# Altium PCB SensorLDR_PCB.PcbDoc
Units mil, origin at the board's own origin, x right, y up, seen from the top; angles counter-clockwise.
Board outline 6000 x 4000 mil, 2 copper layers (Top Layer, Bottom Layer); 19 components, 11 nets, 54 pads, 0 vias.
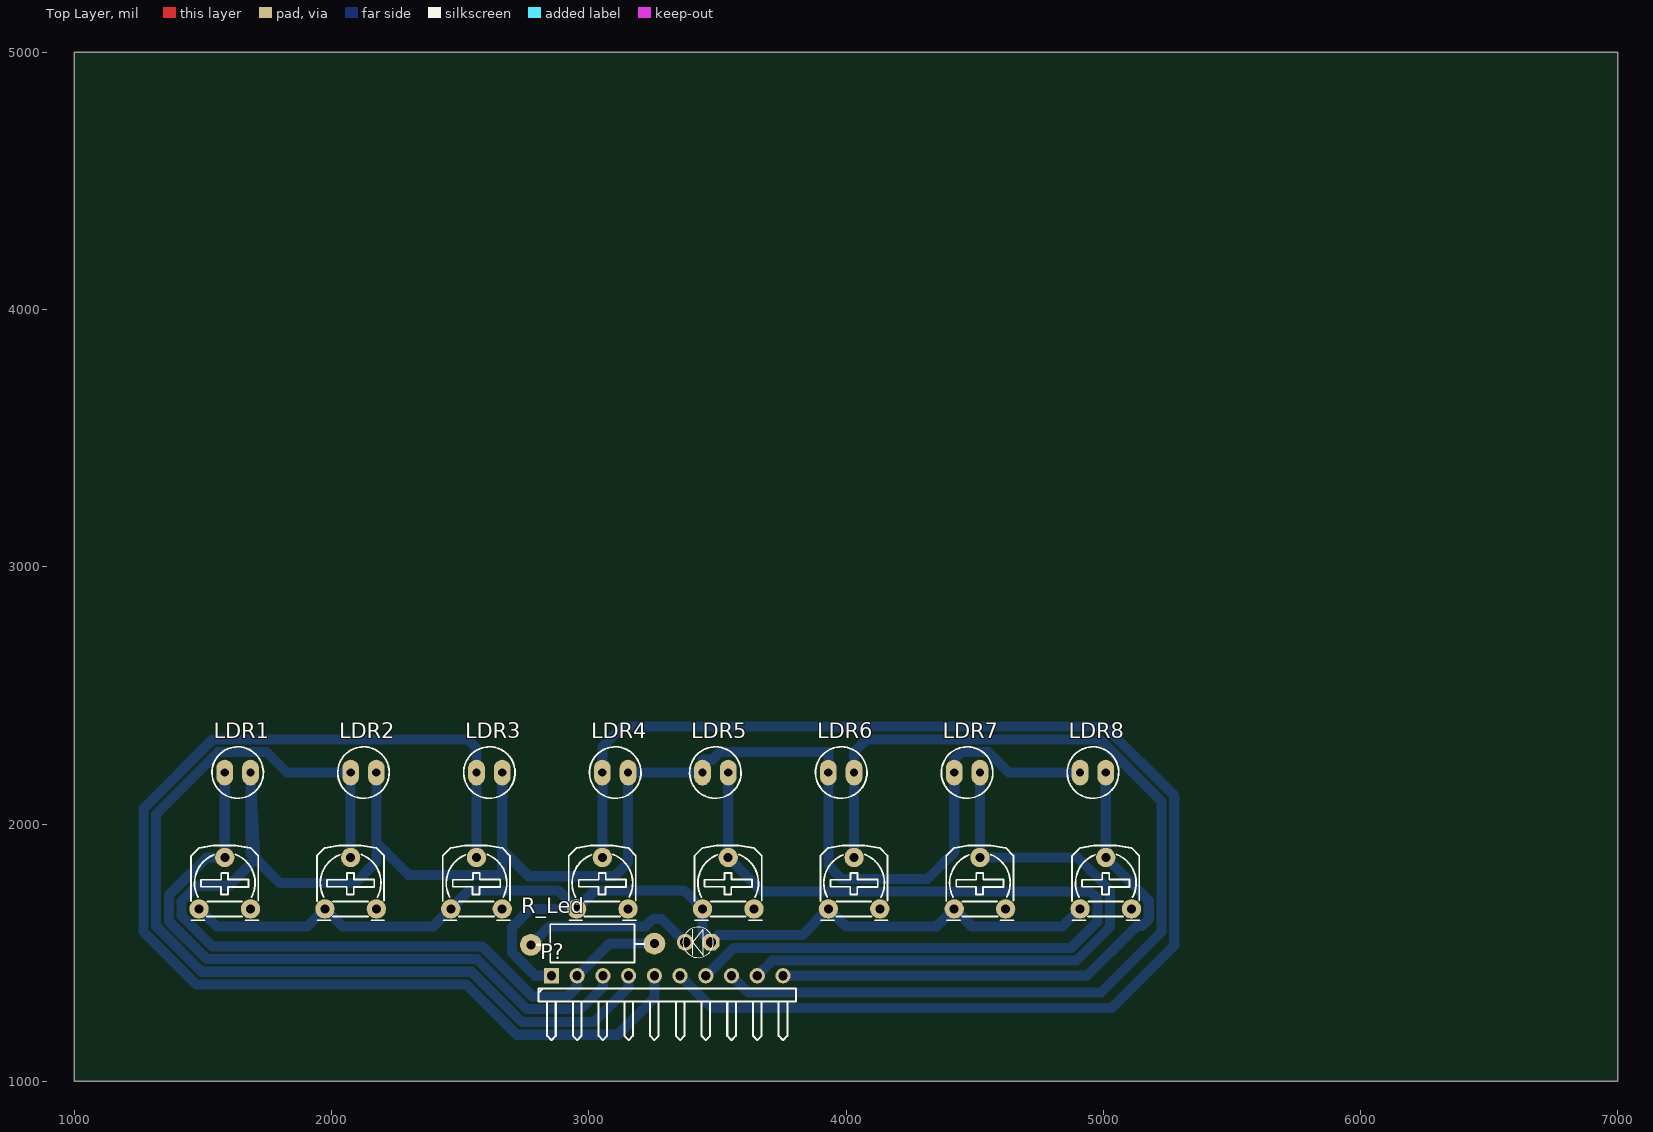
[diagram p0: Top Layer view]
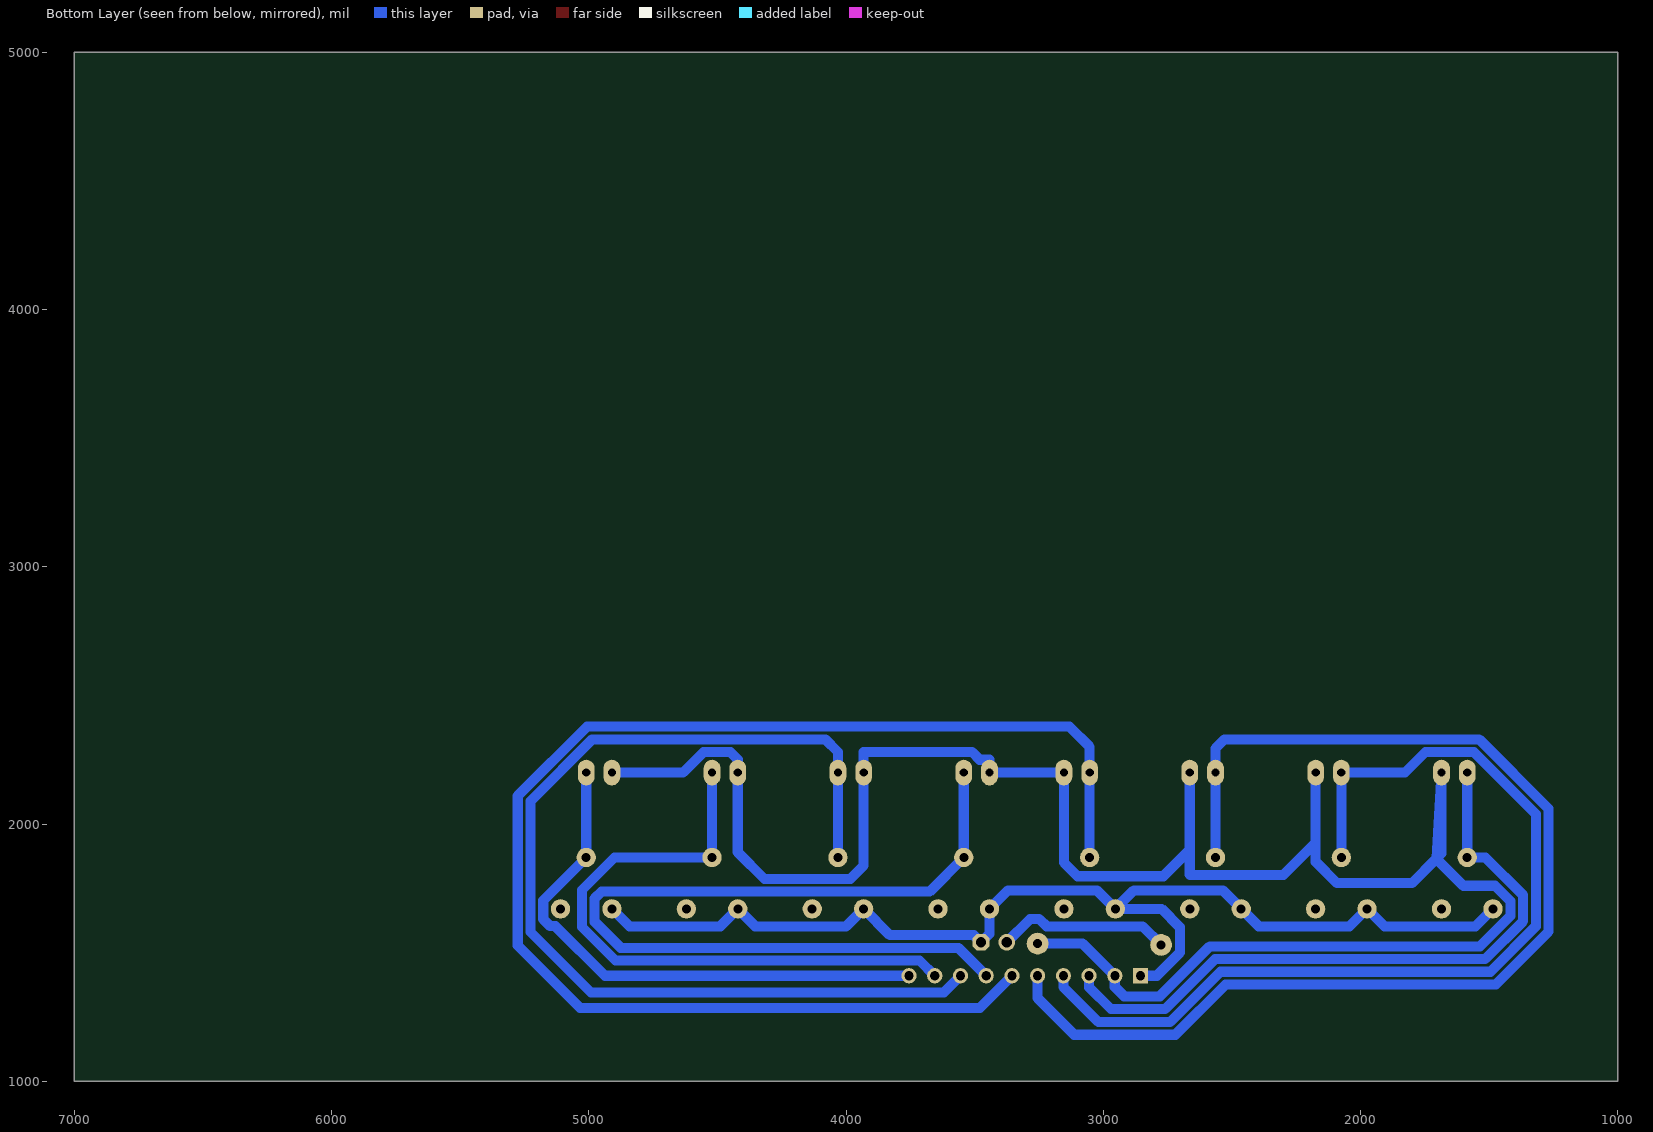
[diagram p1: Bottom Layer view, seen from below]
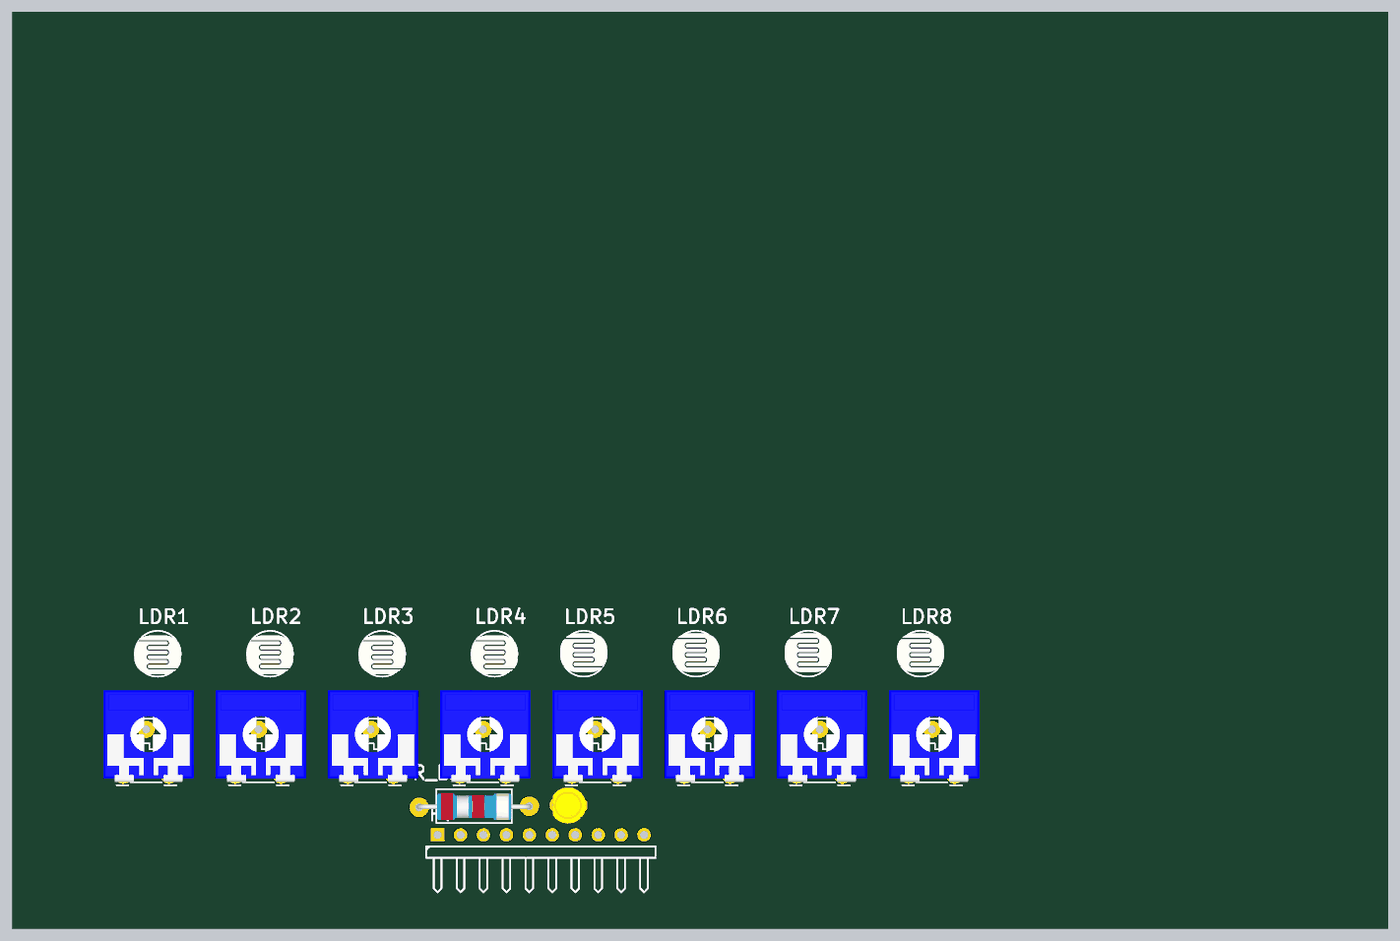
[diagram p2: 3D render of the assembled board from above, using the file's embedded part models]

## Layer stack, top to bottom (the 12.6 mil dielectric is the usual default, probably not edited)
Top Solder: solder mask 0.4, Solder Resist, Dk 3.5
Top Layer: signal copper 1.4
Dielectric 1: dielectric 12.6, FR-4, Dk 4.8
Bottom Layer: signal copper 1.4
Bottom Solder: solder mask 0.4, Solder Resist, Dk 3.5

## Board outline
1000,1000 7000,1000 7000,5000 1000,5000

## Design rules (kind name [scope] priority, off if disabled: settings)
Clearance [All] p1: gap=10 ignorepadtopadclearanceinfootprint=FALSE except(0: Arc-Hole Track-Hole SMDPad-Hole THPad-Hole Via-Hole Fill-Hole Poly-Hole Region-Hole Text-Hole)
PolygonConnect [All] p1: connectstyle=Relief reliefconductorwidth=10 reliefentries=4 polygonreliefangle="90 Angle" airgapwidth=10
RoutingLayers [All] p1: top layer_v5=FALSE bottom layer_v5=TRUE
RoutingVias [All] p1: holewidth=28 width=50 viastyle="Through Hole" minholewidth=28 minwidth=50 maxholewidth=28 maxwidth=50
SolderMaskExpansion [All] p1: expansion=4
Width Others [All] p1: maxlimit=39.37 minlimit=39.37 preferedwidth=39.37
Width VCC [InNet('VCC')] p2: maxlimit=39.37 minlimit=39.37 preferedwidth=39.37
Width GND [InNet('GND')] p3: maxlimit=39.37 minlimit=39.37 preferedwidth=39.37
29 further rules are at their usual default settings.

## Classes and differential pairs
component class SensorLDR: LDR1 LDR2 LDR3 LDR4 LDR5 LDR6 LDR7 LDR8 P? R_Led

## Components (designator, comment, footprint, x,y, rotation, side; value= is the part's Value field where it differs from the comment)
LDR1 "LDR" CDS 1685,2200 r180 top
LDR2 "LDR" CDS 2174.29,2200 r180 top
LDR3 "LDR" CDS 2663.57,2200 r180 top
LDR4 "LDR" CDS 3152.86,2200 r180 top
LDR5 "LDR" CDS 3442.14,2200 r0 top
LDR6 "LDR" CDS 3931.43,2200 r0 top
LDR7 "LDR" CDS 4420.71,2200 r0 top
LDR8 "LDR" CDS 4910,2200 r0 top
LED? "LED" LED-3MM-YELLOW 3475,1540 r180 top value="LED 3 ly Single Colour"
P? "Header 10H" HDR1X10H 2855,1410 r0 top
R_Led "Res" RES-1/2W 2995,1535 r0 top
VR1 "50K" VR-S2 1485,1670 r0 top value="Volume 50k"
VR2 "50K" VR-S2 1974.29,1670 r0 top value="Volume 50k"
VR3 "50K" VR-S2 2463.57,1670 r0 top value="Volume 50k"
VR4 "50K" VR-S2 2952.86,1670 r0 top value="Volume 50k"
VR5 "50K" VR-S2 3442.14,1670 r0 top value="Volume 50k"
VR6 "50K" VR-S2 3931.43,1670 r0 top value="Volume 50k"
VR7 "50K" VR-S2 4420.71,1670 r0 top value="Volume 50k"
VR8 "50K" VR-S2 4910,1670 r0 top value="Volume 50k"

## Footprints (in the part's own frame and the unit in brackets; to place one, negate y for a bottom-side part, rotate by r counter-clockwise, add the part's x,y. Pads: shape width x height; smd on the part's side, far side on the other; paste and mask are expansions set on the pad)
CDS [mil] "QUANG TRO"
  oval 65x100 hole 32: 1(0,0) 2(100,0)
  silkscreen extent -50,-100 150,100, body extent -53,-80 153,89, height 138
HDR1X10H [mm] "Connector; Header; 10 Position; Right Angle"
  rect 1.5x1.5 hole 0.9: 1(0,0)
  round 1.5 hole 0.9: 2(2.54,0) 3(5.08,0) 4(7.62,0) 5(10.16,0) 6(12.7,0) 7(15.24,0) 8(17.78,0) 9(20.32,0) 10(22.86,0)
  silkscreen extent -1.27,-6.35 24.13,-1.27
LED-3MM-YELLOW [mil]
  oct 65x65 hole 40: 1(0,0)
  round 65 hole 40: 2(100,0)
  silkscreen extent -9,-59 109,59, body extent -27,-77 117,80, height 181
RES-1/2W [mil]
  round 85 hole 35: 1(-220,-5) 2(260,0)
  silkscreen extent -195,-74 221,75, body extent -230,-60 270,56, height 121
VR-S2 [mil] "Resistor Variable"
  round 75 hole 35: 1(0,0) 2(100,200) 3(200,0)
  silkscreen extent -31,-44 231,246, body extent -87,-30 307,372, height 165

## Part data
LDR1 LDR2 LDR3 LDR4 LDR5 LDR6 LDR7 LDR8: "Quang Tro"
LED?: "LED Single colour Green and Red"
P?: "Header, 10-Pin, Right Angle"
R_Led: Manufacturer="Generic Components"
VR1 VR2 VR3 VR4 VR5 VR6 VR7 VR8: library part VR-S, "Var Resistor"

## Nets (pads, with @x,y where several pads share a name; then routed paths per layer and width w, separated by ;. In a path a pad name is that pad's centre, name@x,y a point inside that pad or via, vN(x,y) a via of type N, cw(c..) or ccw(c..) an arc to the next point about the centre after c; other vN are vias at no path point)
GND: LDR1.1 LDR2.1 LDR3.1 LDR4.1 LDR5.1 LDR6.1 LDR7.1 LDR8.1 P?.2 R_Led.2 | length 8632.6
  Bottom Layer w39.37: LDR2.1 2174.29,1927.71 ; LDR3.1 2663.57,1900 ; R_Led.2 3080,1535 P?.2 2955,1367 2918.11,1330.11 2779.71,1330.11 2585.45,1524.37 1535.62,1524.37 1417,1642.99 1417,1700 1477,1760 1600,1760 1705,1865 ; LDR8.1 4633,2200 4553.31,2279.69 4450,2279.69 4420.71,2250.4 LDR7.1 4420.71,1890.71 4316.56,1786.56 3983.44,1786.56 3931.43,1838.57 LDR6.1 3931.43,2279.69 3509.69,2279.69 3480,2250 3442.14,2250 LDR5.1 LDR4.1 3152.86,1849.86 3100,1797 2766.57,1797 2663.57,1900 ; 1705,1865 1800,1770 2091,1770 2174.29,1853.29 2174.29,1927.71 ; 1705,1865 1685,1885 LDR1.1 1705,1865 ; 2174.29,1927.71 2300,1802 2662.57,1802 2663.57,1803 2663.57,1900
NetLED?_2: LED?.2 R_Led.1 | length 679.5
  Bottom Layer w39.37: R_Led.1 2847,1602 3220,1602 3249,1631 3284,1631 LED?.2
S1: LDR1.2 P?.3 VR1.2 | length 2617.3
  Bottom Layer w39.37: LDR1.2 VR1.2 1514.53,1870 1367.63,1723.1 1367.63,1622.54 1515.17,1475 2565,1475 2759.26,1280.74 2970.13,1280.74 3055,1365.61 P?.3
S2: LDR2.2 P?.4 VR2.2 | length 3746.7
  Bottom Layer w39.37: VR2.2 LDR2.2 1826.69,2200 1747,2279.69 1559.24,2279.69 1318.26,2038.7 1318.26,1602.09 1494.72,1425.63 2544.37,1425.63 2740,1230 3019,1230 3155,1366 P?.4
S3: LDR3.2 P?.5 VR3.2 | length 4620.6
  Bottom Layer w39.37: VR3.2 LDR3.2 2563.57,2294 2528.52,2329.06 1538.79,2329.06 1268.89,2059.15 1268.89,1581.64 1474.27,1376.26 2523.92,1376.26 2719.55,1180.63 3112.5,1180.63 3255,1323.13 P?.5
S4: LDR4.2 P?.6 VR4.2 | length 5451.7
  Bottom Layer w39.37: VR4.2 LDR4.2 3052.86,2300 3131.28,2378.43 5006.84,2378.43 5275.93,2109.34 5275.93,1527.97 5032.95,1285 3480,1285 P?.6
S5: LDR5.2 P?.7 VR5.2 | length 3530.9
  Bottom Layer w39.37: P?.7 3563.58,1518.58 4875.58,1518.58 4977.19,1620.19 4977.19,1710.81 4950.81,1737.19 3674.96,1737.19 VR5.2 LDR5.2
S6: LDR6.2 P?.8 VR6.2 | length 4029.5
  Bottom Layer w39.37: P?.8 3620,1345 4991.56,1345 5226.56,1580 5226.56,2088.89 4986.39,2329.06 4080.8,2329.06 4031.43,2279.69 LDR6.2 VR6.2
S7: LDR7.2 P?.9 VR7.2 | length 2482.1
  Bottom Layer w39.37: P?.9 3714.21,1469.21 4896.03,1469.21 5026.56,1599.74 5026.56,1743.44 4900,1870 VR7.2 LDR7.2
S8: LDR8.2 P?.10 VR8.2 | length 2152.6
  Bottom Layer w39.37: P?.10 4937,1410 5129.81,1602.81 5150,1602.81 5177.19,1630 5177.19,1702.81 VR8.2 LDR8.2
VCC: LED?.1 P?.1 VR1.1 VR2.1 VR3.1 VR4.1 VR5.1 VR6.1 VR7.1 VR8.1 | length 4503.8
  Bottom Layer w39.37: VR1.1 1553,1602 1906.29,1602 VR2.1 2042.29,1602 2395.57,1602 VR3.1 2535.57,1742 2880.86,1742 VR4.1 ; P?.1 2792,1410 2702,1500 2702,1599 2773,1670 VR4.1 ; VR8.1 4842,1602 4488.71,1602 VR7.1 4352.71,1602 3999.43,1602 VR6.1 3829.38,1567.95 3502.95,1567.95 LED?.1 3442.14,1572.86 VR5.1 3370.14,1742 3024.86,1742 VR4.1
pads on no net: VR1.3 VR2.3 VR3.3 VR4.3 VR5.3 VR6.3 VR7.3 VR8.3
